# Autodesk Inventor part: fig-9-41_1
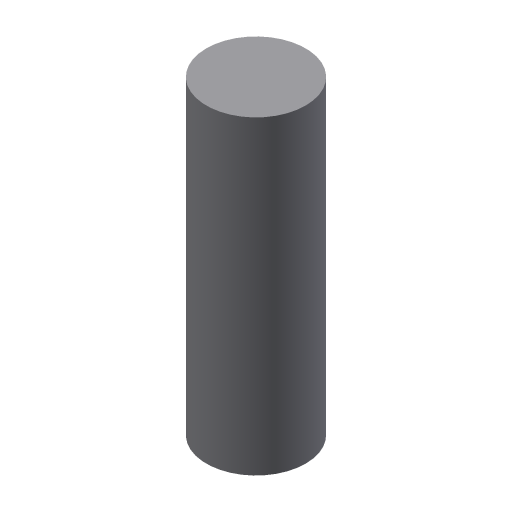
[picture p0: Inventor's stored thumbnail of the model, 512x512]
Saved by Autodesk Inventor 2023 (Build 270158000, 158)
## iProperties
Created: 2013-03
Part Number: fig-9-41_1
Material: Generic
Document SubType Name: Modeling
Designer: CADCIM
Density: 1 g/cm^3
Appearance: Default
Author: CADCIM
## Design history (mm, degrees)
sketch "Sketch1"
  geometry: C1 r 4 at (0, 0); 1 further point
  constraints: 1 centre point, 1 coincident
  dimensions: "d0" = 8 diameter of C1
extrude "Extrusion1" new body sketch "Sketch1" stored distance "d2" = 25; taper "d3" = 0 deg
body "Solid1"
